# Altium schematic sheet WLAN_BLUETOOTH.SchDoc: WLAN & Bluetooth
size A4; Project: STM32MP15-DISCO PI; Date: Not used; ApprovedBy: Not used; CheckedBy: Not used; Author: Not used; CompanyName: STMicroelectronics; DrawnBy: Not used; Engineer: Not used; Organization: Not used; Address1: Not used; Address2: Not used; Address3: Not used; Address4: Not used; DocumentNumber: 9; Revision: Not used; SheetNumber: 9; SheetTotal: 17
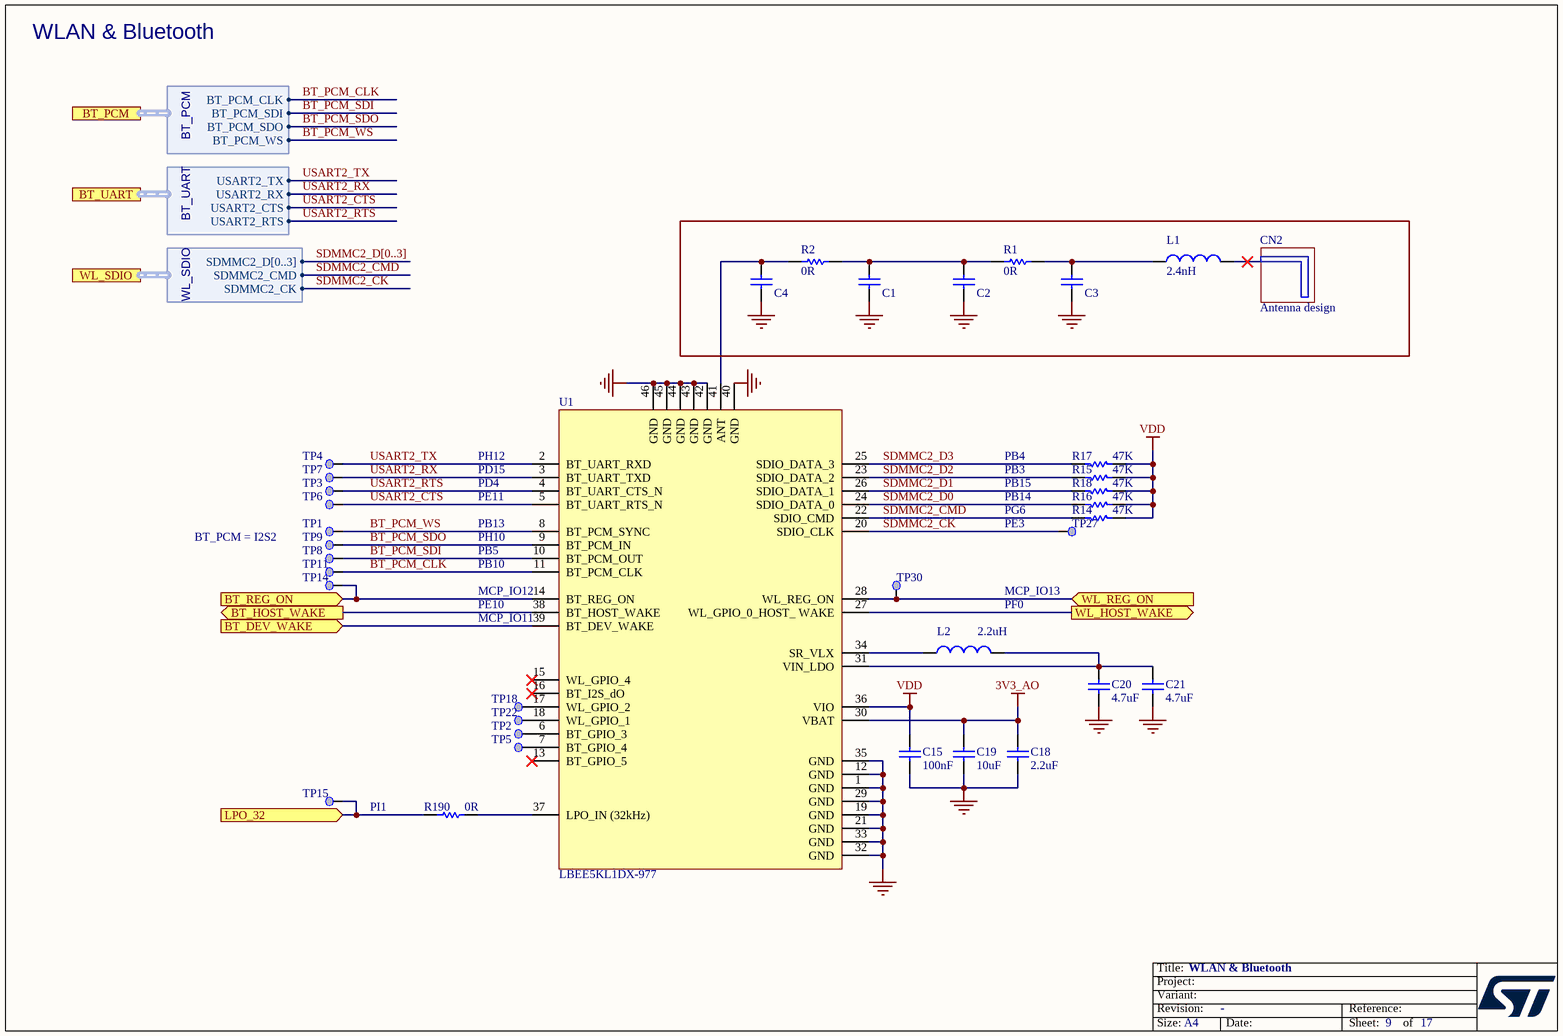
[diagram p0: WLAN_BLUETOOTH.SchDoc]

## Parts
C1  Capacitor  [C0402]  (value not drawn)
C2  Capacitor  [C0402]  (value not drawn)
C3  Capacitor  [C0402]  (value not drawn)
C4  Capacitor  [C0402]  (value not drawn)
C15  value 100nF  [C0402]  (hidden comment: Capacitor)
C18  value 2.2uF  [C0201_H0P5]  (hidden comment: Capacitor)
C19  value 10uF  [C0603]  (hidden comment: Capacitor)
C20  value 4.7uF  [C0402]  (hidden comment: Capacitor)
C21  value 4.7uF  [C0402]  (hidden comment: Capacitor)
CN2  value Antenna design  [ANT_MURATA_TYPE-1-DX_P2ML4452-1-A_DXF]  (hidden comment: antenna_Wifi_BLE_Murata)  (no BOM)
L1  value 2.4nH  [IND_0402_MURATA_LQW15AN2N4C00X]  (hidden comment: Inductor)
L2  value 2.2uH  [L0603]  (hidden comment: Inductor)
R1  value 0R  [R0402]  (hidden comment: Resistor)
R2  value 0R  [R0402]  (hidden comment: Resistor)
R14  value 47K  [R0402]  (hidden comment: Resistor)
R15  value 47K  [R0402]  (hidden comment: Resistor)
R16  value 47K  [R0402]  (hidden comment: Resistor)
R17  value 47K  [R0402]  (hidden comment: Resistor)
R18  value 47K  [R0402]  (hidden comment: Resistor)
R190  value 0R  [R0402]  (hidden comment: Resistor)
TP1  Test Point  [TP_SMD_1MM]  (value not drawn)  (no BOM)
TP2  Test Point  [TP_SMD_1MM]  (value not drawn)  (no BOM)
TP3  Test Point  [TP_SMD_1MM]  (value not drawn)  (no BOM)
TP4  Test Point  [TP_SMD_1MM]  (value not drawn)  (no BOM)
TP5  Test Point  [TP_SMD_1MM]  (value not drawn)  (no BOM)
TP6  Test Point  [TP_SMD_1MM]  (value not drawn)  (no BOM)
TP7  Test Point  [TP_SMD_1MM]  (value not drawn)  (no BOM)
TP8  Test Point  [TP_SMD_1MM]  (value not drawn)  (no BOM)
TP9  Test Point  [TP_SMD_1MM]  (value not drawn)  (no BOM)
TP11  Test Point  [TP_SMD_1MM]  (value not drawn)  (no BOM)
TP14  Test Point  [TP_SMD_1MM]  (value not drawn)  (no BOM)
TP15  Test Point  [TP_SMD_1MM]  (value not drawn)  (no BOM)
TP18  Test Point  [TP_SMD_1MM]  (value not drawn)  (no BOM)
TP22  Test Point  [TP_SMD_1MM]  (value not drawn)  (no BOM)
TP27  Test Point  [TP_SMD_1MM]  (value not drawn)  (no BOM)
TP30  Test Point  [TP_SMD_1MM]  (value not drawn)  (no BOM)
U1  value LBEE5KL1DX-977  [MOD_WLAN-BT_MURATA_LBEE5KL1DX-883]  (hidden comment: LBEE5KL1DX-883)

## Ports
BT_DEV_WAKE (in), BT_HOST_WAKE (out), BT_PCM (harness BT_PCM), BT_REG_ON (in), BT_UART (harness BT_UART), LPO_32 (in), WL_HOST_WAKE (out), WL_REG_ON (in), WL_SDIO (harness WL_SDIO)

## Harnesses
BT_PCM: BT_PCM_CLK, BT_PCM_SDI, BT_PCM_SDO, BT_PCM_WS
BT_UART: USART2_TX, USART2_RX, USART2_CTS, USART2_RTS
WL_SDIO: SDMMC2_D[0..3], SDMMC2_CMD, SDMMC2_CK

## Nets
3V3_AO: C18.2 C19.2 U1.30(VBAT)
GND: C1.1 C2.1 C3.1 C4.1 C15.1 C18.1 C19.1 C20.1 C21.1 U1.1(GND) U1.12(GND) U1.19(GND) U1.21(GND) U1.29(GND) U1.32(GND) U1.33(GND) U1.35(GND) U1.40(GND) U1.42(GND) U1.43(GND) U1.44(GND) U1.45(GND) U1.46(GND)
VDD: C15.2 R14.1 R15.1 R16.1 R17.1 R18.1 U1.36(VIO)
BT_DEV_WAKE: U1.39(BT_DEV_WAKE) ; port BT_DEV_WAKE
BT_HOST_WAKE: U1.38(BT_HOST_WAKE) ; port BT_HOST_WAKE
BT_PCM_CLK: TP11.1 U1.11(BT_PCM_CLK) ; port BT_PCM.BT_PCM_CLK
BT_PCM_SDI: TP8.1 U1.10(BT_PCM_OUT) ; port BT_PCM.BT_PCM_SDI
BT_PCM_SDO: TP9.1 U1.9(BT_PCM_IN) ; port BT_PCM.BT_PCM_SDO
BT_PCM_WS: TP1.1 U1.8(BT_PCM_SYNC) ; port BT_PCM.BT_PCM_WS
BT_REG_ON: TP14.1 U1.14(BT_REG_ON) ; port BT_REG_ON
LPO_32: R190.1 TP15.1 ; port LPO_32
SDMMC2_CK: TP27.1 U1.20(SDIO_CLK) ; port WL_SDIO.SDMMC2_CK
SDMMC2_CMD: R14.2 U1.22(SDIO_CMD) ; port WL_SDIO.SDMMC2_CMD
SDMMC2_D0: R16.2 U1.24(SDIO_DATA_0)
SDMMC2_D1: R18.2 U1.26(SDIO_DATA_1)
SDMMC2_D2: R15.2 U1.23(SDIO_DATA_2)
SDMMC2_D3: R17.2 U1.25(SDIO_DATA_3)
USART2_CTS: TP6.1 U1.5(BT_UART_RTS_N) ; port BT_UART.USART2_CTS
USART2_RTS: TP3.1 U1.4(BT_UART_CTS_N) ; port BT_UART.USART2_RTS
USART2_RX: TP7.1 U1.3(BT_UART_TXD) ; port BT_UART.USART2_RX
USART2_TX: TP4.1 U1.2(BT_UART_RXD) ; port BT_UART.USART2_TX
WL_HOST_WAKE: U1.27(WL_GPIO_0_HOST__WAKE) ; port WL_HOST_WAKE
WL_REG_ON: TP30.1 U1.28(WL_REG_ON) ; port WL_REG_ON
NetC1_2: C1.2 C2.2 R1.2 R2.1
NetC3_2: C3.2 L1.1 R1.1
NetC4_2: C4.2 R2.2 U1.41(ANT)
NetC20_2: C20.2 C21.2 L2.2 U1.31(VIN_LDO)
NetL2_1: L2.1 U1.34(SR_VLX)
NetR190_2: R190.2 U1.37(LPO_IN_(32kHz))
NetTP2_1: TP2.1 U1.6(BT_GPIO_3)
NetTP5_1: TP5.1 U1.7(BT_GPIO_4)
NetTP18_1: TP18.1 U1.17(WL_GPIO_2)
NetTP22_1: TP22.1 U1.18(WL_GPIO_1)

Not connected (* = marked no-connect by the designer): L1 2*; U1 13(BT_GPIO_5)* 15(WL_GPIO_4)* 16(BT_I2S_dO)*

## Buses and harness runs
bus SDMMC2_D[0..3]

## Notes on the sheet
- WLAN & Bluetooth
- PD15
- PH12
- PD4
- PE11
- PG6
- PB14
- PB15
- PB3
- PB4
- BT_PCM = I2S2
- PB10
- PB5
- PH10
- PB13
- PE3
- PE10
- (near U1) MCP_IO11
- (near U1) MCP_IO12
- (near L2) PF0
- MCP_IO13
- PI1

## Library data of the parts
C1-C4 = MCD-00200: Capacitor, MLCC, 12pF, 50V, NPO, +/-5%, 0402, T=0.5mm; Manufacturer_Part_Number: CC0402JRNPO9BN120; Manufacturer: YAGEO; Part_Preference: Recommended; Component_Country_Of_Origin: China; ShowFields: YES; ID: 2667
C15 = MCD-00006: Capacitor, MLCC, 100nF, 16V, X7R, +/-10%, 0402, T=0.5mm; Manufacturer_Part_Number: CC0402KRX7R7BB104; Manufacturer: YAGEO; Part_Preference: Recommended; Partial_Alternate_Internal_Part_Number: MCD-03299; Order_Code_RS: 9402047; Component_Country_Of_Origin: China; ShowFields: YES; ID: 2474
C18 = MCD-02235: Capacitor, MLCC, 2.2uF, 10V, X5R,+/-10%, 0201, T=0.5mm; Manufacturer_Part_Number: GRM033R61A225KE47; Manufacturer: MURATA; Part_Preference: Recommended; Order_Code_RS: NA; Component_Country_Of_Origin: Japan°°; ShowFields: YES; ID: 4335
C19 = MCD-00099: Capacitor, MLCC, 10uF, 10V, X5R, +/-10%, 0603, T=0.8mm; Manufacturer_Part_Number: GRM188R61A106KE69; Manufacturer: MURATA; Part_Preference: Recommended; Partial_Alternate_Internal_Part_Number: MCD-03152; Order_Code_RS: 2494233; Component_Country_Of_Origin: Japan°°; ShowFields: YES; ID: 2770
C20 C21 = MCD-01356: Capacitor, MLCC, 4.7uF, 6V3, X5R, +/-20%, 0402, T=0.5mm; Manufacturer_Part_Number: GRM155R60J475ME47; Manufacturer: MURATA; Part_Preference: Recommended; Partial_Alternate_Internal_Part_Number: MCD-04455; Order_Code_RS: 814-5230; Component_Country_Of_Origin: Japan°°; ShowFields: YES; ID: 3456
CN2 = MCD-00656: Murata_Type1DX_AntennaDesign_P2ML4452-1-A.DXF; Part_Type: Misc; Manufacturer: MURATA; Part_Preference: Recommended; Component_Country_Of_Origin: Unknown; ShowFields: YES; ID: 3086
L1 = MCD-00657: Inductor, 2.4nH, +/-0.2nH, Itemp=850mA, 50R, 0402, T=0.6mm, Qmin=20; Manufacturer_Part_Number: LQW15AN2N4C00#; Manufacturer: MURATA; Part_Preference: Recommended; Order_Code_RS: 177-6240; Component_Country_Of_Origin: Japan°°; ShowFields: YES; ID: 3088
L2 = MCD-00659: Inductor, 2.2uH, +/-20%, 1050mA, 0R2, 0603, T=1mm; Manufacturer_Part_Number: LQM18PN2R2MGH; Manufacturer: MURATA; Part_Preference: Recommended; Component_Country_Of_Origin: Japan°°; ShowFields: YES; ID: 3085
R1 R2 = MCD-00052: Resistor, 0R, 0402, +/-5%, 1/16W; Manufacturer_Part_Number: RC0402JR-070RL; Manufacturer: YAGEO; Part_Preference: Recommended; Order_Code_RS: 9232516RL; Component_Country_Of_Origin: China; ShowFields: YES; ID: 2540
R14-R18 = MCD-00063: Resistor, 47K, 0402, +/-1%, 1/16W; Manufacturer_Part_Number: RC0402FR-0747KL; Manufacturer: YAGEO; Part_Preference: Recommended; Order_Code_RS: 9239430; Component_Country_Of_Origin: China; ShowFields: YES; ID: 2528
R190 = MCD-00052: Resistor, 0R, 0402, +/-5%, 1/16W; Part_Preference: Recommended; Manufacturer: YAGEO; Manufacturer_Part_Number: RC0402JR-070RL; Order_Code_RS: 9232516RL; Component_Country_Of_Origin: China; ShowFields: YES; ID: 2540
TP1-TP9 TP11 TP14 TP15 TP18 TP22 TP27 TP30 = MCD-00074: Test Point 1mm; Part_Type: Misc; Part_Preference: Recommended; ShowFields: YES; ID: 2518; Component_Country_Of_Origin: Unknown
U1 = MCD-00268: IEEE802.11b/g/n W-LAN + Bluetooth 4.1+EDR module; Manufacturer: MURATA; Part_Type: IC; Part_Preference: Recommended; Component_Country_Of_Origin: Japan°°; ShowFields: YES; ID: 2603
